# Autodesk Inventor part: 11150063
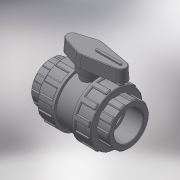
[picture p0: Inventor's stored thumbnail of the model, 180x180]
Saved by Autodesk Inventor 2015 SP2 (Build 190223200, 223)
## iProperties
Created: 2017-11
Part Number: 11150063
Material: Generic
Description: PLASSON 2/NUT VALVE CEM. PVC 63
Document SubType Name: Modeling
Designer: KIM
Density: 1 g/cm^3
Appearance: Default
Author: KIM
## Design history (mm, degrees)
derived "111500.ipt"
feature "Solid1::111500.ipt"
tag "TaggingFeature1"
body "Solid1"
other parameters: "d0" = 169, "d1" = 63, "d2" = 118, "d3" = 38, "d4" = 50.4, "d5" = 26.6, "d7" = 88.2, "d8" = 106.2, "d13" = 1.89, "d23" = 38, "d24" = 113.28, "d25" = 1.26, "d26" = 1.89, "d27" = 17.7, "d28" = 8.85, "d29" = 28.5, "d30" = 0, "d35" = 1.89, "d39" = 59, "d45" = 360 deg, "d47" = 1.26, "d50" = 64.9, "d51" = 35.4, "d53" = 0, "d55" = 12.6, "d56" = 6.3, "d57" = 26.6, "d58" = 0, "d59" = 1.89, "d61" = 360 deg, "d63" = 47.2, "d64" = 106, "d66" = 129, "d68" = 23.6, "d69" = 38.7, "d70" = 26.5, "d71" = 3 deg, "d73" = 2.36, "d74" = 51.6, "d75" = 3.18, "d76" = 0, "d77" = 1.26, "d_" = 63, "l_" = 38, "H_" = 169, "K_" = 118, "F_" = 106, "J_" = 129, "d67" = 47.2, "d72" = 11.8
